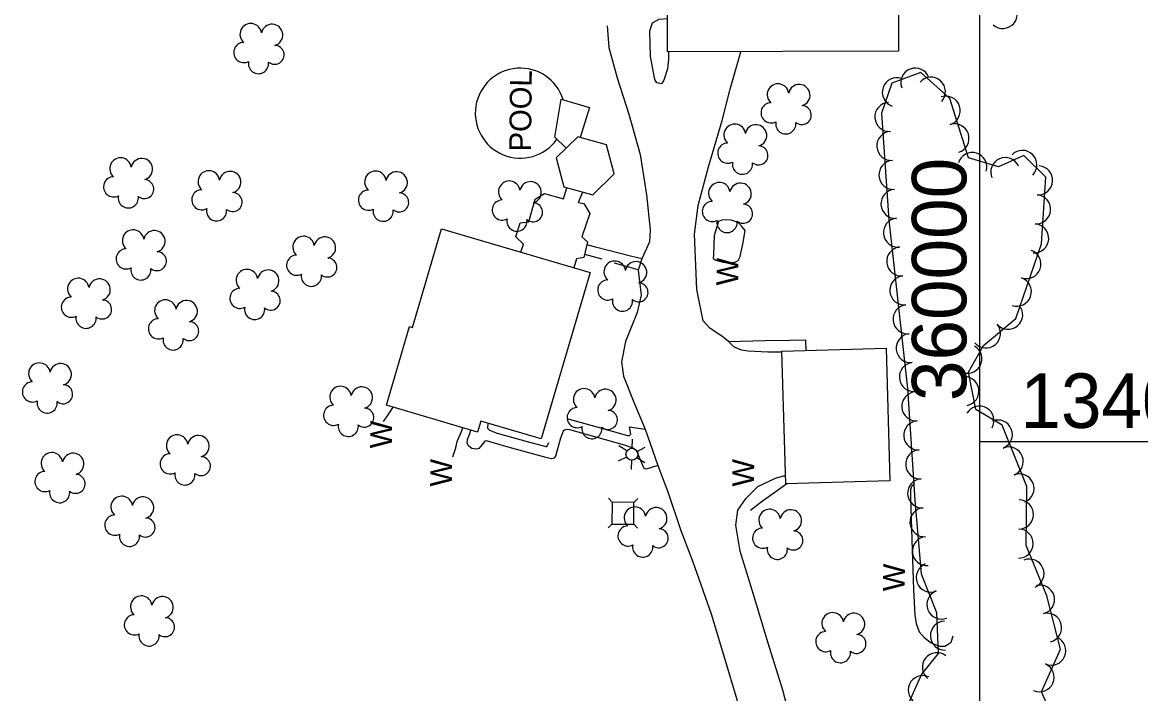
# Model space of a CAD drawing. Extents: x 353423 to 364002, y 127000 to 201942.
# Drawn here: x 359736.3 to 360044.2, y 133930.6 to 134115.3 of the extents above; entities that cross this region are included whole.
import ezdxf

# ---------------------------------------------------------------- set-up
doc = ezdxf.new("R2010")
doc.units = 0
for name, color, linetype in [('E_DTM_SlopeBottom', 7, 'Continuous'), ('E_FEN_Generic', 7, 'Continuous'), ('E_LAND_BrushLine', 7, 'Continuous'), ('E_LAND_TreeLine', 7, 'Continuous'), ('E_MISCPROP', 7, 'Continuous'), ('E_SGN', 7, 'Continuous'), ('E_WTR_FlowLine', 7, 'Continuous')]:
    doc.layers.add(name, color=color, linetype=linetype)

msp = doc.modelspace()

# ---------------------------------------------------------------- linework, layer by layer
at = {"layer": 'E_DTM_SlopeBottom'}
msp.add_lwpolyline([(359928.02, 134060.51), (359926.76, 134056.66), (359926.58, 134051.39), (359926.52, 134050.36), (359927.28, 134049.87), (359929.29, 134049.37), (359932.27, 134049.31), (359933.36, 134049.85), (359933.96, 134050.93), (359934.68, 134054.29), (359935.29, 134058.04), (359934.53, 134059.13), (359933.4, 134060.27), (359931.5, 134060.93), (359929.87, 134061.04), (359928.89, 134060.94)], close=True, dxfattribs=at)
for points in [[(359838.33, 134009.43), (359836.54, 134006.84), (359835.61, 134005.49)], [(359854.79, 133995.75), (359855.67, 133998.3), (359856, 133999.99), (359857.21, 134002.8), (359857.54, 134003.78)], [(359946.76, 133988.35), (359943.47, 133986.01), (359940.1, 133983.58), (359936.83, 133980.99)], [(359981.92, 133988.51), (359981.11, 133987.59), (359980.89, 133986.61), (359980.82, 133984.5), (359981.32, 133970.22), (359981.71, 133959.3), (359982.07, 133952.19), (359982.38, 133949.96), (359983.24, 133947.68), (359984.6, 133946.04), (359986.54, 133944.57), (359988.88, 133943.69), (359990.34, 133943.69), (359991.27, 133944.23), (359992.03, 133944.82), (359992.58, 133946.5)]]:
    msp.add_lwpolyline(points, dxfattribs=at)
at = {"layer": 'E_FEN_Generic'}
msp.add_lwpolyline([(360023.37, 133916.66), (360016.91, 133931.13), (360022.13, 133942.89), (360018.42, 133957.52), (360012.71, 133971.41), (360012.93, 133987.61), (360006.14, 134004.51), (359998.81, 134008.8), (359996.84, 134019.08), (360000.96, 134026.42), (360009.84, 134033.9), (360016.93, 134054.42), (360018.16, 134072.71), (360012.09, 134078.67), (360005.06, 134075.6), (359996.88, 134078.05), (359991.68, 134094.44), (359983.68, 134101.57), (359975.74, 134098.59), (359972.87, 134090.33), (359974.94, 134060.92), (359980.03, 134014.63), (359982.1, 133983.88), (359983.78, 133963.58), (359988, 133952.96), (359988.46, 133941.68), (359983.93, 133936.01), (359978.54, 133924.09)], dxfattribs=at)
for centre, radius, start, end in [((360006.26, 134117.67), 4, 229.1283, 49.113), ((359799.17, 134112.07), 2.97, 7.7946, 229.0284), ((359805.02, 134111.89), 2.97, 285.4454, 168.4187), ((359797.26, 134107.05), 2.78, 90.7655, 298.5384), ((359805.73, 134106.42), 2.61, 230.1506, 88.0832), ((359801.3, 134104), 2.78, 167.4425, 8.4535), ((359982.19, 134098.77), 4, 20.5573, 200.542), ((359944.38, 134095.47), 2.97, 7.7946, 229.0284), ((359977.09, 134096.11), 4, 70.849, 250.8337), ((359986.48, 134096.27), 4, 318.281, 138.2657), ((359950.23, 134095.3), 2.97, 285.4454, 168.4187), ((359942.47, 134090.45), 2.78, 90.7655, 298.5384), ((359950.93, 134089.82), 2.61, 230.1506, 88.0832), ((359975.04, 134089.33), 4, 94.0276, 274.0123), ((359990.56, 134091.04), 4, 287.6221, 107.6068), ((359932.45, 134084.38), 2.97, 7.7946, 229.0284), ((359938.3, 134084.21), 2.97, 285.4454, 168.4187), ((359946.51, 134087.41), 2.78, 167.4425, 8.4535), ((359992.98, 134083.42), 4, 287.6221, 107.6068), ((359975.6, 134081.35), 4, 94.0276, 274.0123), ((359930.54, 134079.36), 2.78, 90.7655, 298.5384), ((359939, 134078.73), 2.61, 230.1506, 88.0832), ((360011.69, 134076.12), 4, 315.599, 135.5836), ((359763.31, 134075.11), 2.97, 7.7946, 229.0284), ((359769.16, 134074.94), 2.97, 285.4454, 168.4187), ((359934.58, 134076.32), 2.78, 167.4425, 8.4535), ((359976.16, 134073.37), 4, 94.0276, 274.0123), ((359997.91, 134075.56), 4, 343.3188, 163.3035), ((360006.96, 134074.15), 4, 23.5756, 203.5603), ((359787.62, 134071.55), 2.97, 7.7946, 229.0284), ((359793.47, 134071.38), 2.97, 285.4454, 168.4187), ((359833.5, 134071.44), 2.97, 7.7946, 229.0284), ((359839.35, 134071.27), 2.97, 285.4454, 168.4187), ((360016.01, 134071.87), 4, 266.1455, 86.1301), ((359761.4, 134070.09), 2.78, 90.7655, 298.5384), ((359769.87, 134069.46), 2.61, 230.1506, 88.0832), ((359870.36, 134068.73), 2.97, 7.7946, 229.0284), ((359876.21, 134068.55), 2.97, 285.4454, 168.4187), ((359928.21, 134068.33), 2.97, 7.7946, 229.0284), ((359934.06, 134068.15), 2.97, 285.4454, 168.4187), ((359765.44, 134067.05), 2.78, 167.4425, 8.4535), ((359785.71, 134066.53), 2.78, 90.7655, 298.5384), ((359794.18, 134065.9), 2.61, 230.1506, 88.0832), ((359831.59, 134066.42), 2.78, 90.7655, 298.5384), ((359840.06, 134065.79), 2.61, 230.1506, 88.0832), ((359976.72, 134065.39), 4, 94.0276, 274.0123), ((360015.47, 134063.89), 4, 266.1455, 86.1301), ((359868.45, 134063.7), 2.78, 90.7655, 298.5384), ((359876.92, 134063.07), 2.61, 230.1506, 88.0832), ((359926.3, 134063.31), 2.78, 90.7655, 298.5384), ((359934.77, 134062.68), 2.61, 230.1506, 88.0832), ((359789.75, 134063.49), 2.78, 167.4425, 8.4535), ((359835.63, 134063.38), 2.78, 167.4425, 8.4535), ((359977.42, 134057.51), 4, 96.2909, 276.2756), ((359766.77, 134055.28), 2.97, 7.7946, 229.0284), ((359872.49, 134060.66), 2.78, 167.4425, 8.4535), ((359930.34, 134060.26), 2.78, 167.4425, 8.4535), ((360014.93, 134055.91), 4, 266.1455, 86.1301), ((359772.62, 134055.11), 2.97, 285.4454, 168.4187), ((359813.73, 134053.54), 2.97, 7.7946, 229.0284), ((359819.58, 134053.37), 2.97, 285.4454, 168.4187), ((359764.86, 134050.26), 2.78, 90.7655, 298.5384), ((359773.33, 134049.63), 2.61, 230.1506, 88.0832), ((359978.29, 134049.56), 4, 96.2909, 276.2756), ((360012.78, 134048.82), 4, 250.9501, 70.9347), ((359811.82, 134048.52), 2.78, 90.7655, 298.5384), ((359820.29, 134047.89), 2.61, 230.1506, 88.0832), ((359899.41, 134046.71), 2.97, 7.7946, 229.0284), ((359905.26, 134046.54), 2.97, 285.4454, 168.4187), ((359768.9, 134047.22), 2.78, 167.4425, 8.4535), ((359798.11, 134044.42), 2.97, 7.7946, 229.0284), ((359803.97, 134044.25), 2.97, 285.4454, 168.4187), ((359815.86, 134045.48), 2.78, 167.4425, 8.4535), ((359751.68, 134041.98), 2.97, 7.7946, 229.0284), ((359757.53, 134041.81), 2.97, 285.4454, 168.4187), ((359897.5, 134041.69), 2.78, 90.7655, 298.5384), ((359905.97, 134041.06), 2.61, 230.1506, 88.0832), ((359979.17, 134041.6), 4, 96.2909, 276.2756), ((360010.17, 134041.26), 4, 250.9501, 70.9347), ((359796.2, 134039.4), 2.78, 90.7655, 298.5384), ((359804.67, 134038.77), 2.61, 230.1506, 88.0832), ((359749.77, 134036.96), 2.78, 90.7655, 298.5384), ((359758.24, 134036.33), 2.61, 230.1506, 88.0832), ((359775.66, 134036.03), 2.97, 7.7946, 229.0284), ((359781.51, 134035.86), 2.97, 285.4454, 168.4187), ((359800.24, 134036.36), 2.78, 167.4425, 8.4535), ((359901.54, 134038.65), 2.78, 167.4425, 8.4535), ((359980.05, 134033.65), 4, 96.2909, 276.2756), ((360007.77, 134034.9), 4, 220.1364, 40.121), ((359753.81, 134033.92), 2.78, 167.4425, 8.4535), ((359773.75, 134031.01), 2.78, 90.7655, 298.5384), ((359782.22, 134030.38), 2.61, 230.1506, 88.0832), ((360001.65, 134029.74), 4, 220.1364, 40.121), ((359777.79, 134027.97), 2.78, 167.4425, 8.4535), ((359980.92, 134025.7), 4, 96.2909, 276.2756), ((359996.53, 134022.8), 4, 240.6934, 60.6781), ((359740.96, 134018.67), 2.97, 7.7946, 229.0284), ((359746.81, 134018.5), 2.97, 285.4454, 168.4187), ((359981.8, 134017.75), 4, 96.2909, 276.2756), ((359739.04, 134013.65), 2.78, 90.7655, 298.5384), ((359747.51, 134013.02), 2.61, 230.1506, 88.0832), ((359823.9, 134012.24), 2.97, 7.7946, 229.0284), ((359995.71, 134013.86), 4, 280.8442, 100.8288), ((359829.75, 134012.07), 2.97, 285.4454, 168.4187), ((359890.98, 134011.61), 2.97, 7.7946, 229.0284), ((359896.83, 134011.44), 2.97, 285.4454, 168.4187), ((359982.46, 134009.69), 4, 93.8446, 273.8293), ((359743.09, 134010.61), 2.78, 167.4425, 8.4535), ((359821.98, 134007.22), 2.78, 90.7655, 298.5384), ((359830.45, 134006.59), 2.61, 230.1506, 88.0832), ((359889.07, 134006.59), 2.78, 90.7655, 298.5384), ((359999.86, 134005.76), 4, 329.709, 149.6937), ((359897.54, 134005.96), 2.61, 230.1506, 88.0832), ((360004.92, 134001.93), 4, 291.8975, 111.8821), ((359826.03, 134004.18), 2.78, 167.4425, 8.4535), ((359893.11, 134003.55), 2.78, 167.4425, 8.4535), ((359983, 134001.71), 4, 93.8446, 273.8293), ((359778.89, 133998.88), 2.97, 7.7946, 229.0284), ((359784.75, 133998.71), 2.97, 285.4454, 168.4187), ((359744.4, 133994.01), 2.97, 7.7946, 229.0284), ((359750.25, 133993.84), 2.97, 285.4454, 168.4187), ((359983.53, 133993.73), 4, 93.8446, 273.8293), ((360007.91, 133994.51), 4, 291.8975, 111.8821), ((359776.98, 133993.86), 2.78, 90.7655, 298.5384), ((359785.45, 133993.23), 2.61, 230.1506, 88.0832), ((359742.49, 133988.99), 2.78, 90.7655, 298.5384), ((359750.96, 133988.36), 2.61, 230.1506, 88.0832), ((359781.02, 133990.82), 2.78, 167.4425, 8.4535), ((360010.89, 133987.08), 4, 291.8975, 111.8821), ((359984.07, 133985.75), 4, 93.8446, 273.8293), ((359746.53, 133985.94), 2.78, 167.4425, 8.4535), ((359763.63, 133982), 2.97, 7.7946, 229.0284), ((359769.48, 133981.82), 2.97, 285.4454, 168.4187), ((359904.98, 133979.04), 2.97, 7.7946, 229.0284), ((359910.83, 133978.87), 2.97, 285.4454, 168.4187), ((359942.06, 133978.42), 2.97, 7.7946, 229.0284), ((359984.7, 133977.81), 4, 94.7424, 274.7271), ((360010.73, 133979.92), 4, 269.2126, 89.1973), ((359761.72, 133976.98), 2.78, 90.7655, 298.5384), ((359770.19, 133976.34), 2.61, 230.1506, 88.0832), ((359947.91, 133978.25), 2.97, 285.4454, 168.4187), ((359903.07, 133974.02), 2.78, 90.7655, 298.5384), ((359911.54, 133973.39), 2.61, 230.1506, 88.0832), ((359940.15, 133973.4), 2.78, 90.7655, 298.5384), ((359948.62, 133972.77), 2.61, 230.1506, 88.0832), ((360010.62, 133971.92), 4, 269.2126, 89.1973), ((359765.76, 133973.93), 2.78, 167.4425, 8.4535), ((359985.36, 133969.84), 4, 94.7424, 274.7271), ((359907.11, 133970.97), 2.78, 167.4425, 8.4535), ((359944.19, 133970.35), 2.78, 167.4425, 8.4535), ((359986.42, 133962.59), 4, 111.6824, 291.6671), ((360013.63, 133963.66), 4, 292.3741, 112.3587), ((360016.52, 133956.52), 4, 284.224, 104.2087), ((359769.02, 133954.57), 2.97, 7.7946, 229.0284), ((359774.87, 133954.39), 2.97, 285.4454, 168.4187), ((359989.38, 133955.16), 4, 111.6824, 291.6671), ((359767.11, 133949.55), 2.78, 90.7655, 298.5384), ((359775.58, 133948.92), 2.61, 230.1506, 88.0832), ((359959.44, 133949.96), 2.97, 7.7946, 229.0284), ((359965.29, 133949.79), 2.97, 285.4454, 168.4187), ((359990.36, 133946.59), 4, 92.348, 272.3327), ((360018.48, 133948.77), 4, 284.224, 104.2087), ((359957.53, 133944.94), 2.78, 90.7655, 298.5384), ((359771.15, 133946.5), 2.78, 167.4425, 8.4535), ((359966, 133944.31), 2.61, 230.1506, 88.0832), ((360019.64, 133942.45), 4, 246.0674, 66.052), ((359961.57, 133941.9), 2.78, 167.4425, 8.4535), ((359988.12, 133937.89), 4, 51.3495, 231.3342), ((360016.4, 133935.14), 4, 246.0674, 66.052), ((359984.23, 133931.58), 4, 65.6922, 245.6769)]:
    msp.add_arc(centre, radius, start, end, dxfattribs=at)
at = {"layer": 'E_LAND_BrushLine'}
for p, q in [((359904.17, 133998.15), (359904.27, 134000.67)), ((359902.72, 133997.43), (359900.5, 133998.82)), ((359905.61, 133997.25), (359907.8, 133998.47)), ((359902.69, 133995.73), (359900.38, 133994.56)), ((359904.05, 133994.88), (359903.95, 133992.28)), ((359905.54, 133995.62), (359907.72, 133994.23))]:
    msp.add_line(p, q, dxfattribs=at)
msp.add_circle((359904.13, 133996.51), 1.64, dxfattribs=at)
at = {"layer": 'E_LAND_TreeLine'}
for p, q in [((360000, 132500), (360000, 135000)), ((360000, 134000), (364000, 134000))]:
    msp.add_line(p, q, dxfattribs=at)
at = {"layer": 'E_MISCPROP'}
for points in [[(359897.33, 134114.36), (359897.8, 134108.44), (359900.1, 134100.07), (359903.33, 134090.12), (359906.38, 134079.03), (359908.13, 134067.89), (359909.18, 134058.23), (359908.95, 134054.97), (359906.87, 134050.25), (359905.89, 134047.16), (359906.68, 134040.26), (359905.57, 134035.54), (359902.4, 134027.57), (359901.29, 134021.93), (359901.82, 134017.97), (359904.67, 134010.84), (359907.79, 134003.45), (359911.29, 133993.45), (359914.03, 133986.16), (359917.63, 133975.51), (359920.91, 133966.86), (359925.96, 133952.56), (359929.34, 133941.31), (359933.32, 133928.1)], [(359914.19, 134107.2), (359914.19, 134105.26), (359913.96, 134102.54), (359912.97, 134099.4), (359912.26, 134098.48), (359911.02, 134098.7), (359910.48, 134099.62), (359909.25, 134105.98), (359909.11, 134113.04), (359909.83, 134115.21), (359911.62, 134116.23), (359913.91, 134116.4)], [(359945.47, 134024.57), (359941.59, 134024.64), (359936.11, 134024.88), (359934.32, 134025.15), (359932.2, 134026.08), (359930.74, 134027.56), (359929.23, 134028.76), (359925.6, 134031.21), (359923.76, 134033.23), (359922.05, 134041.87), (359921.35, 134057.07), (359922.41, 134064.94), (359925.27, 134075.63), (359928.95, 134088.32), (359931.21, 134096.94), (359934.1, 134107.26)], [(359906.87, 134050.25), (359903.73, 134051.02), (359894.13, 134053.5), (359891.73, 134054.13)], [(359891.12, 134051.58), (359895.85, 134050.29)], [(359905.9, 134047.21), (359902.69, 134048.14), (359899.33, 134049.12)], [(359930.74, 134027.56), (359940.73, 134027.79), (359947.63, 134027.93), (359951.92, 134028.02), (359952.05, 134025.02)], [(359886.25, 134006.35), (359894.44, 134004.04), (359902.96, 134001.62), (359903.44, 134001.67), (359903.83, 134002.05), (359903.51, 134004.01), (359907.79, 134003.45)], [(359911.29, 133993.45), (359908.03, 133992.37), (359907.54, 133992.59), (359907.38, 133992.81), (359905.54, 133997.32), (359905.17, 133997.7), (359904.35, 133998.19), (359902.08, 133998.96), (359887.05, 134003.2), (359886.18, 134003.31), (359885.59, 134003.15), (359885.21, 134002.88), (359884.49, 134000.92), (359883.12, 133995.99), (359882.68, 133995.45), (359881.97, 133995.29), (359881.21, 133995.4), (359870.1, 133998.42), (359864.07, 134000.18), (359863.64, 134000.13), (359862.88, 133999.16), (359862, 133998.07), (359861.3, 133997.86), (359860.05, 133998.08), (359859.24, 133998.74), (359858.75, 133999.55), (359858.86, 134000.58), (359859.47, 134002.21), (359859.76, 134003.12)], [(359864.59, 134005.05), (359864.36, 134004.15), (359864.36, 134003.66), (359864.9, 134003.11), (359867.01, 134002.35), (359875.31, 133999.98), (359880.47, 133998.61), (359880.68, 133998.66), (359880.9, 133998.87), (359881.23, 133999.74)], [(359949.03, 133918.9), (359945.71, 133931.56), (359941.68, 133944.55), (359937.66, 133957.93), (359933.96, 133969.88), (359932.73, 133977), (359933.29, 133981.12), (359935.64, 133984.43), (359938.85, 133987.67), (359943.64, 133989.94), (359945.92, 133990.53), (359946.46, 133990.54)]]:
    msp.add_lwpolyline(points, dxfattribs=at)
at = {"layer": 'E_SGN'}
for p, q in [((359898.71, 133983.31), (359897.66, 133984.38)), ((359905.78, 133984.29), (359904.71, 133983.24)), ((359898.65, 133977.31), (359897.57, 133976.26)), ((359905.69, 133976.17), (359904.64, 133977.24))]:
    msp.add_line(p, q, dxfattribs=at)
msp.add_lwpolyline([(359904.64, 133977.24), (359904.71, 133983.24), (359898.71, 133983.31), (359898.65, 133977.31)], close=True, dxfattribs=at)
at = {"layer": 'E_WTR_FlowLine'}
for points in [[(359977.57, 134107.41), (359913.94, 134107.2), (359913.82, 134144.28), (359977.45, 134144.49)], [(359897.18, 134081.67), (359889.21, 134083.87), (359883.32, 134078.07), (359885.39, 134070.08), (359893.37, 134067.88), (359899.26, 134073.67)], [(359851.71, 134058.55), (359892.6, 134046.52), (359879.14, 134000.77), (359862.56, 134005.64), (359861.65, 134002.57), (359836.51, 134009.97), (359842.89, 134031.66), (359843.72, 134031.41)], [(359946.53, 133988.34), (359945.46, 134024.83), (359974.13, 134025.67), (359975.19, 133989.17)]]:
    msp.add_lwpolyline(points, close=True, dxfattribs=at)
for points in [[(359886.01, 134080.73), (359882.92, 134083.72), (359884.63, 134094.23), (359892.47, 134091.95), (359889.89, 134083.68)], [(359873.59, 134052.11), (359874.29, 134054.34), (359872.21, 134056.36), (359873.4, 134060.19), (359875.74, 134060.44), (359877.51, 134066.7), (359880.11, 134068.27), (359885.28, 134066.83), (359886.21, 134069.85)], [(359890.55, 134068.65), (359889.37, 134065.82), (359890.87, 134065.48), (359892.53, 134062.71), (359890.34, 134056.29), (359891.92, 134054.95), (359890.9, 134050.69), (359888.9, 134050.28), (359888.14, 134047.83)]]:
    msp.add_lwpolyline(points, dxfattribs=at)
msp.add_ellipse((359873.39, 134090.37), major_axis=(3.21, -11.96), ratio=0.999978, start_param=1.611476, end_param=6.972177, dxfattribs=at)

# ---------------------------------------------------------------- texts
at = {"layer": 'E_DTM_SlopeBottom'}
for p in [(359933.41, 134042.91), (359838.04, 133998.09), (359854.57, 133987.57), (359937.75, 133987.55), (359979.26, 133958.77)]:
    msp.add_text('W', height=6, rotation=89.3709, dxfattribs=at).set_placement(p)
at = {"layer": 'E_LAND_TreeLine'}
msp.add_text('  360000  ', height=15, rotation=90, dxfattribs=at).set_placement((359996.25, 134000))
msp.add_text('  134000  ', height=15, dxfattribs=at).set_placement((360000, 134003.75))
at = {"layer": 'E_WTR_FlowLine'}
msp.add_text('POOL', height=6, rotation=89.3709, dxfattribs=at).set_placement((359876.35, 134079.81))

doc.saveas('drawing.dxf')
